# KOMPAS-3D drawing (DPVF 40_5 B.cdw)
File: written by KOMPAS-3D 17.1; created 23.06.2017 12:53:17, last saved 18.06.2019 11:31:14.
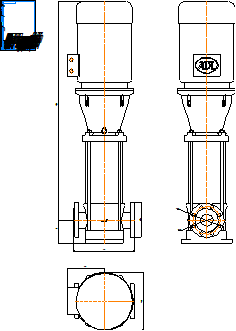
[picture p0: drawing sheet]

Sheet 1: A4, portrait

Title block, sheet 1: name: DPVF 40_5 B; material: Внимание! Данный продукт является объектом авторского права ООО «Торговый Дом АДЛ». / Запрещается изменение, копирование, распространение / (в том числе путем копирования на другие сайты и ресурсы в Интернете) / или любое иное использование информации и объектов без предварительного / согласия правообладателя (ООО «Торговый Дом АДЛ»).; scale: 1:1; sheets: 1; organisation: ООО "Торговый дом АДЛ"; sheet format: A4; stored path: C:\Клочков АВ\Насосы\DP PAMS\DPVF 40\Компас 2d\DPVF 40_5 B.cdw

Views: Спереди 1
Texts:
  Клочков АВ
  ООО АДЛ ГРУПП
Dimensions and other numbers on the sheet: 365; 223; 350; 1312,5; 140; 209,6; 168,1; 76,2; 1:1; 1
